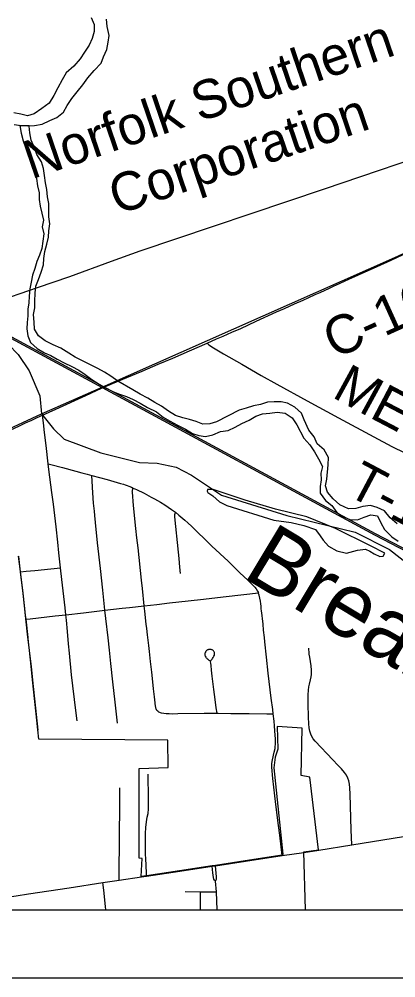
# Model space of a CAD drawing. Extents: x 0 to 34, y 0 to 22.
# Drawn here: x 3.054 to 3.607, y 13.717 to 15.128 of the extents above; entities that cross this region are included whole.
import ezdxf

# ---------------------------------------------------------------- set-up
doc = ezdxf.new("R2010")
doc.units = 0
for name, color, linetype in [('GM_X_City_Street', 7, 'Continuous'), ('GM_X_Corporation', 7, 'Continuous'), ('GM_X_County_Road', 7, 'Continuous'), ('GM_X_County_Road_Text', 7, 'Continuous'), ('GM_X_Major_River', 7, 'Continuous'), ('GM_X_Minor_Lake', 7, 'Continuous'), ('GM_X_Minor_River', 7, 'Continuous'), ('GM_X_Minor_River_Text', 7, 'Continuous'), ('GM_X_Rail_Line', 7, 'Continuous'), ('GM_X_Rail_Line_Text', 7, 'Continuous'), ('GM_X_State_Route', 7, 'Continuous'), ('GM_X_Township_Road', 7, 'Continuous'), ('GM_X_Township_Road_Text', 7, 'Continuous'), ('SH_Data', 7, 'Continuous')]:
    doc.layers.add(name, color=color, linetype=linetype)

msp = doc.modelspace()

# ---------------------------------------------------------------- linework, layer by layer
at = {"layer": 'GM_X_City_Street'}
for points in [[(3.2006, 13.8608), (3.2006, 13.8697), (3.2016, 13.974), (3.2016, 13.997)], [(3.3424, 13.8596), (3.3409, 13.8607), (3.3398, 13.8624), (3.3394, 13.8647), (3.3385, 13.8715), (3.3374, 13.8814)], [(3.3424, 13.8596), (3.3435, 13.8622), (3.3436, 13.8657), (3.3422, 13.8821)], [(3.1808, 13.8173), (3.1805, 13.8222), (3.178, 13.8462), (3.1768, 13.8574)], [(3.3448, 13.8173), (3.3438, 13.8438), (3.3424, 13.8596)], [(3.2976, 13.8441), (3.3201, 13.844), (3.3438, 13.8438)], [(3.3203, 13.8173), (3.3201, 13.8368), (3.3201, 13.844)]]:
    msp.add_lwpolyline(points, dxfattribs=at)
at = {"layer": 'GM_X_Corporation'}
for points in [[(4.732, 17.2135), (3.7259, 17.2107), (3.5941, 17.2097), (3.4848, 17.2088), (3.0597, 17.2067), (2.6493, 17.2102), (2.5952, 17.2097), (2.159, 17.2055), (2.114, 17.2048), (2.114, 13.8173), (5.0539, 13.8173)], [(2.114, 13.8173), (3.4743, 13.8173), (3.472, 13.9024), (3.4938, 13.9058), (3.4807, 14.0124), (3.4679, 14.015), (3.4696, 14.0846), (3.4327, 14.0869), (3.4339, 14.0539), (3.43, 14.0419), (3.4281, 14.0264), (3.4388, 13.9229), (3.4413, 13.8991), (3.4401, 13.8975), (3.386, 13.8896), (3.342, 13.8827), (3.3372, 13.8819), (3.2894, 13.8748), (3.2406, 13.8674), (3.2331, 13.8663), (3.2346, 13.8929), (3.2301, 13.8935), (3.2299, 14.025), (3.2724, 14.0267), (3.2721, 14.0668), (3.0825, 14.0685), (3.0812, 14.0822), (3.0786, 14.1054), (3.0748, 14.1418), (3.0734, 14.1556), (3.0713, 14.1759), (3.0681, 14.2033), (3.0665, 14.2182), (3.0635, 14.2453), (3.0628, 14.2509), (3.0613, 14.2652), (3.0594, 14.2832), (3.0555, 14.3152), (3.0527, 14.3374)]]:
    msp.add_lwpolyline(points, dxfattribs=at)
at = {"layer": 'GM_X_County_Road'}
for points in [[(3.3301, 14.6508), (3.3437, 14.6571), (3.3533, 14.6613), (3.3664, 14.667), (3.3795, 14.6727), (3.402, 14.6832), (3.4318, 14.6969), (3.4437, 14.7021), (3.4584, 14.7087), (3.4709, 14.7144), (3.4796, 14.7183), (3.4886, 14.7224), (3.4961, 14.7256), (3.5099, 14.732), (3.5158, 14.7347), (3.5255, 14.7392), (3.5381, 14.7449), (3.5525, 14.7514), (3.5744, 14.7611), (3.6003, 14.7732), (3.6263, 14.7851)], [(3.0879, 14.545), (3.1073, 14.5538), (3.1516, 14.5741), (3.1747, 14.5845), (3.1907, 14.5915), (3.2119, 14.6002), (3.2344, 14.6097), (3.2581, 14.62), (3.2793, 14.629), (3.304, 14.6396), (3.3301, 14.6508)], [(3.0404, 14.5231), (3.0529, 14.5289), (3.0628, 14.5335), (3.0723, 14.5378), (3.0802, 14.5414), (3.0879, 14.545)]]:
    msp.add_lwpolyline(points, dxfattribs=at)
at = {"layer": 'GM_X_Major_River'}
for points in [[(3.046, 14.9726), (3.0558, 14.9711), (3.066, 14.9708), (3.0763, 14.9713), (3.0876, 14.9733), (3.0985, 14.9783), (3.1087, 14.9829), (3.1189, 14.9909), (3.1241, 15.0008), (3.1308, 15.0111), (3.1387, 15.0207), (3.147, 15.031), (3.1544, 15.0413), (3.1638, 15.0523), (3.174, 15.0627), (3.1777, 15.0722), (3.1825, 15.0832), (3.1843, 15.0938), (3.1861, 15.1037), (3.183, 15.1166), (3.1818, 15.1276)], [(3.1594, 15.1301), (3.1637, 15.1195), (3.1637, 15.1096), (3.1608, 15.099), (3.1563, 15.0891), (3.1496, 15.0788), (3.1432, 15.0693), (3.1339, 15.0582), (3.1226, 15.0486), (3.1166, 15.0383), (3.1103, 15.0265), (3.1047, 15.0151), (3.0976, 15.004), (3.0867, 14.9964), (3.0757, 14.9883), (3.0656, 14.9852)], [(3.0656, 14.9852), (3.0561, 14.9878), (3.0455, 14.99)]]:
    msp.add_lwpolyline(points, dxfattribs=at)
at = {"layer": 'GM_X_Minor_Lake'}
msp.add_line((3.4766, 14.3956), (3.4303, 14.4066), dxfattribs=at)
msp.add_lwpolyline([(3.4303, 14.4066), (3.386, 14.4199), (3.3389, 14.4355), (3.3302, 14.4358), (3.3298, 14.4331), (3.331, 14.4313), (3.3382, 14.4264), (3.3481, 14.4174), (3.3588, 14.4121), (3.4278, 14.3907), (3.4532, 14.3871), (3.4722, 14.3827), (3.4892, 14.3767), (3.4961, 14.3677), (3.5003, 14.3609), (3.5084, 14.3522), (3.5205, 14.3455), (3.5346, 14.3422), (3.5508, 14.3465), (3.5625, 14.3477), (3.5693, 14.3451), (3.5754, 14.341), (3.5838, 14.3369), (3.5887, 14.3377), (3.5909, 14.3422), (3.57, 14.3527), (3.5184, 14.3785), (3.4766, 14.3956)], dxfattribs=at)
at = {"layer": 'GM_X_Minor_River'}
msp.add_line((3.0683, 14.9709), (3.0544, 14.9713), dxfattribs=at)
for points in [[(3.0544, 14.9713), (3.0567, 14.9597), (3.0594, 14.9484), (3.064, 14.9374), (3.0694, 14.9272), (3.0718, 14.9159), (3.0756, 14.9045), (3.0791, 14.8932), (3.0804, 14.8826), (3.0831, 14.8723), (3.0832, 14.8625), (3.0844, 14.8526), (3.0871, 14.842), (3.0891, 14.8318), (3.0873, 14.8219), (3.09, 14.8117), (3.0882, 14.8011), (3.0871, 14.7904), (3.0834, 14.7806), (3.0793, 14.771), (3.0768, 14.7608), (3.0734, 14.7509), (3.0712, 14.7406), (3.0694, 14.7308), (3.0684, 14.7201), (3.0677, 14.7103), (3.0662, 14.7008), (3.0663, 14.6913), (3.0653, 14.6814), (3.0646, 14.6719), (3.0662, 14.6617), (3.0704, 14.6519), (3.0799, 14.6432), (3.0906, 14.6369), (3.1001, 14.6328), (3.1096, 14.6272), (3.1198, 14.6219), (3.1309, 14.6167), (3.1411, 14.6111), (3.1506, 14.6047), (3.1605, 14.5976), (3.1712, 14.5908), (3.1807, 14.5852), (3.1913, 14.5796), (3.2012, 14.5759), (3.2114, 14.5726), (3.2213, 14.5681), (3.2312, 14.5629), (3.2422, 14.5561), (3.2555, 14.5498), (3.2654, 14.5423), (3.2757, 14.5363), (3.2863, 14.5303), (3.2981, 14.5243), (3.3084, 14.5179), (3.3179, 14.515), (3.3277, 14.5135), (3.3383, 14.5163), (3.3496, 14.5209), (3.3606, 14.5225), (3.3711, 14.5275), (3.3809, 14.5329), (3.3915, 14.5379), (3.4013, 14.5433), (3.4111, 14.5472), (3.4221, 14.548), (3.433, 14.5492), (3.4444, 14.5478), (3.455, 14.5411), (3.4616, 14.5309), (3.4723, 14.5112), (3.4807, 14.5014), (3.4876, 14.4913), (3.4937, 14.4807), (3.4995, 14.4697), (3.4969, 14.4595), (3.4974, 14.45), (3.4959, 14.4401), (3.496, 14.4303), (3.5037, 14.4197), (3.5132, 14.4122), (3.5208, 14.402), (3.5304, 14.3953), (3.5398, 14.3915), (3.5508, 14.3912), (3.5606, 14.3951), (3.5705, 14.3982), (3.5803, 14.3968), (3.5853, 14.3866), (3.5907, 14.3768), (3.6014, 14.3662), (3.6109, 14.3595)], [(3.4481, 14.5626), (3.4386, 14.5645), (3.4284, 14.5648), (3.4185, 14.5639), (3.4083, 14.5608), (3.3981, 14.5585), (3.3872, 14.5553), (3.377, 14.5522), (3.3438, 14.5353), (3.334, 14.5322), (3.3238, 14.5317), (3.3139, 14.5358), (3.3041, 14.5384), (3.2942, 14.541), (3.2836, 14.5443), (3.2729, 14.5507), (3.263, 14.5582), (3.2531, 14.5638), (3.2425, 14.5698), (3.2315, 14.5761), (3.2208, 14.5821), (3.1988, 14.5948), (3.1885, 14.6023), (3.179, 14.6083), (3.1691, 14.6136), (3.1573, 14.6196), (3.1478, 14.6244), (3.1361, 14.6304), (3.1265, 14.636), (3.1148, 14.6435), (3.1034, 14.6487), (3.092, 14.6543), (3.0821, 14.6615), (3.0759, 14.6716), (3.0755, 14.6819), (3.0746, 14.6933), (3.0764, 14.7031), (3.0764, 14.7126), (3.077, 14.7244), (3.0781, 14.735), (3.0822, 14.7445), (3.0859, 14.7555), (3.0892, 14.7662), (3.0899, 14.7757), (3.0913, 14.7859), (3.0943, 14.7966), (3.0968, 14.8068), (3.0971, 14.8163), (3.0986, 14.8266), (3.097, 14.8368), (3.0973, 14.8467), (3.0972, 14.8565), (3.0952, 14.8664), (3.0944, 14.877), (3.0924, 14.8868), (3.0908, 14.8978), (3.0892, 14.9077), (3.0865, 14.9179), (3.0796, 14.9284), (3.0761, 14.9383), (3.0711, 14.9496), (3.0692, 14.9602), (3.0683, 14.9704), (3.0683, 14.9709)], [(3.6092, 14.3852), (3.5992, 14.3939), (3.5905, 14.4041), (3.5798, 14.4093), (3.57, 14.4119), (3.5586, 14.4106), (3.5484, 14.4075), (3.5378, 14.4071), (3.5249, 14.413), (3.5154, 14.4217), (3.507, 14.4315), (3.5039, 14.4413), (3.5057, 14.4508), (3.5078, 14.4721), (3.5081, 14.4827), (3.502, 14.494), (3.4917, 14.503), (3.4874, 14.5133), (3.4794, 14.5231), (3.4725, 14.5382), (3.4686, 14.548), (3.4587, 14.557), (3.4481, 14.5626)]]:
    msp.add_lwpolyline(points, dxfattribs=at)
at = {"layer": 'GM_X_Rail_Line'}
msp.add_line((3.0863, 14.5472), (3.1757, 14.5864), dxfattribs=at)
for points in [[(3.0149, 14.7105), (3.0803, 14.7326), (3.128, 14.7488), (3.1891, 14.7717), (3.2313, 14.7866), (3.5025, 14.8781), (3.6902, 14.9419)], [(3.1757, 14.5864), (3.6056, 14.777), (3.709, 14.8243), (3.8008, 14.858), (3.9746, 14.9077), (4.0254, 14.9101), (4.301, 14.9178), (4.3473, 14.9048), (4.5823, 14.8024), (4.7517, 14.7573), (4.9245, 14.7137), (5.0662, 14.6846), (5.2252, 14.6792), (5.2963, 14.6779)], [(2.9747, 14.6894), (3.0232, 14.6639), (3.0523, 14.6345), (3.0682, 14.6103), (3.0838, 14.5735), (3.0863, 14.5472)], [(4.608, 13.8331), (4.5607, 13.8486), (4.517, 13.8684), (4.4694, 13.8906), (4.4269, 13.9136), (4.0464, 14.124), (3.5762, 14.3684), (3.1759, 14.5851), (3.0416, 14.6578)], [(4.6088, 13.8353), (4.5616, 13.8508), (4.5179, 13.8705), (4.4705, 13.8927), (4.4281, 13.9157), (4.0475, 14.126), (3.5773, 14.3705), (3.177, 14.5871), (3.0427, 14.6599)], [(2.114, 14.2044), (2.3759, 14.309), (2.8221, 14.4454), (3.0247, 14.5187), (3.0863, 14.5472)], [(3.0863, 14.5472), (3.1041, 14.5249), (3.1199, 14.5095), (3.1737, 14.4896), (3.2303, 14.4753), (3.2566, 14.4744), (3.2842, 14.4686), (3.3069, 14.4566), (3.351, 14.4272), (3.4469, 14.3972), (3.5477, 14.3728), (3.598, 14.3474), (3.6632, 14.2963), (3.7477, 14.2257), (3.826, 14.1572), (3.8816, 14.1151), (4.0933, 13.9137), (4.1465, 13.842), (4.1621, 13.8173)]]:
    msp.add_lwpolyline(points, dxfattribs=at)
at = {"layer": 'GM_X_State_Route'}
for p, q in [((3.4404, 13.897), (3.4722, 13.9018)), ((3.4722, 13.9018), (3.494, 13.9052))]:
    msp.add_line(p, q, dxfattribs=at)
for points in [[(3.494, 13.9052), (3.5427, 13.9129), (3.6188, 13.925), (3.6622, 13.932), (3.7942, 13.952), (3.9385, 13.974)], [(3.2333, 13.8657), (3.2408, 13.8669), (3.2896, 13.8742), (3.3374, 13.8814), (3.3422, 13.8821), (3.3862, 13.889), (3.4404, 13.897)], [(3.0224, 13.834), (3.0332, 13.8354), (3.0493, 13.8379), (3.0675, 13.8408), (3.1269, 13.8499), (3.1768, 13.8574), (3.2006, 13.8608), (3.2333, 13.8657)]]:
    msp.add_lwpolyline(points, dxfattribs=at)
at = {"layer": 'GM_X_Township_Road'}
for points in [[(3.3301, 14.6508), (3.3317, 14.6492), (3.3334, 14.6478), (3.3369, 14.6455), (3.3538, 14.6354), (3.3807, 14.6202), (3.4091, 14.6036), (3.4324, 14.5906), (3.4771, 14.5662), (3.5228, 14.5412), (3.5751, 14.513), (3.6015, 14.4991), (3.6203, 14.4895)], [(3.0963, 14.4736), (3.0932, 14.5002), (3.0909, 14.5193), (3.0893, 14.5335), (3.0879, 14.545)], [(3.0963, 14.4736), (3.1, 14.4726), (3.1171, 14.468), (3.137, 14.4626), (3.1456, 14.4602), (3.1535, 14.458), (3.1606, 14.4561)], [(3.1141, 14.3203), (3.1119, 14.3424), (3.1104, 14.3583), (3.108, 14.3806), (3.1042, 14.414), (3.1018, 14.4312), (3.0973, 14.465), (3.0963, 14.4736)], [(3.1606, 14.4561), (3.183, 14.4502), (3.2027, 14.4447), (3.2071, 14.4433), (3.2093, 14.4426), (3.2124, 14.4415), (3.2148, 14.4405), (3.2185, 14.439), (3.2212, 14.4378)], [(3.1795, 14.2583), (3.1765, 14.2877), (3.1732, 14.3192), (3.1689, 14.3574), (3.1658, 14.3871), (3.1648, 14.3972), (3.1641, 14.4038), (3.163, 14.4155), (3.162, 14.431), (3.1609, 14.4478), (3.1606, 14.4561)], [(3.2375, 14.2646), (3.2347, 14.2899), (3.2332, 14.3022), (3.2285, 14.3498), (3.2267, 14.3645), (3.2253, 14.3782), (3.2218, 14.4123), (3.22, 14.4315), (3.2199, 14.4327), (3.22, 14.4337), (3.2202, 14.4347), (3.2212, 14.4378)], [(3.2212, 14.4378), (3.2262, 14.4356), (3.2371, 14.4302), (3.2476, 14.4246), (3.2525, 14.422), (3.2614, 14.4169), (3.2679, 14.4129), (3.2727, 14.4098), (3.2775, 14.4064), (3.2832, 14.4021)], [(3.2907, 14.312), (3.2899, 14.3214), (3.2887, 14.3342), (3.2879, 14.3433), (3.2826, 14.3956), (3.2826, 14.3987), (3.2827, 14.4003), (3.2832, 14.4021)], [(3.2832, 14.4021), (3.2883, 14.398), (3.2969, 14.3907), (3.3013, 14.3868), (3.3075, 14.381), (3.3119, 14.3769), (3.3304, 14.3587)], [(3.3304, 14.3587), (3.3368, 14.3524), (3.3608, 14.33), (3.3781, 14.3129), (3.3896, 14.3024), (3.3926, 14.2995), (3.3963, 14.2958), (3.3982, 14.2938), (3.3999, 14.2918), (3.4019, 14.2893), (3.4038, 14.2863), (3.4053, 14.2836)], [(3.0557, 14.3146), (3.0529, 14.3369), (3.0528, 14.3378)], [(3.0557, 14.3146), (3.0637, 14.3154), (3.0766, 14.3166), (3.1003, 14.3189), (3.1141, 14.3203)], [(3.0637, 14.2448), (3.063, 14.2504), (3.0615, 14.2646), (3.0596, 14.2827), (3.0557, 14.3146)], [(3.1222, 14.2514), (3.121, 14.2616), (3.119, 14.2784), (3.1161, 14.3031), (3.1141, 14.3203)], [(3.2375, 14.2646), (3.2558, 14.2666), (3.2745, 14.2689), (3.2884, 14.2704), (3.32, 14.2737), (3.358, 14.2781), (3.4053, 14.2836)], [(3.4174, 14.1891), (3.4149, 14.2118), (3.4142, 14.2178), (3.413, 14.2289), (3.4121, 14.2376), (3.4112, 14.2459), (3.4107, 14.2498), (3.4103, 14.2543), (3.41, 14.2568), (3.4095, 14.2608), (3.4091, 14.264), (3.4087, 14.2673), (3.4082, 14.2714), (3.4074, 14.276), (3.4064, 14.2802), (3.4059, 14.2819), (3.4053, 14.2836)], [(3.0637, 14.2448), (3.0698, 14.2455), (3.1065, 14.2497), (3.1222, 14.2514), (3.1483, 14.2544), (3.1795, 14.2583)], [(3.1795, 14.2583), (3.2048, 14.261), (3.2159, 14.2622), (3.2375, 14.2646)], [(3.198, 14.0918), (3.1946, 14.1226), (3.1912, 14.1528), (3.1883, 14.1796), (3.1862, 14.1992), (3.1842, 14.2174), (3.1809, 14.2457), (3.1795, 14.2583)], [(3.2584, 14.1087), (3.2572, 14.1094), (3.2561, 14.1104), (3.2554, 14.1116), (3.2549, 14.1128), (3.2546, 14.114), (3.2545, 14.1153), (3.2542, 14.1165), (3.2535, 14.122), (3.2525, 14.1306), (3.2511, 14.1423), (3.25, 14.1528), (3.2485, 14.1671), (3.2468, 14.1825), (3.2451, 14.1973), (3.2442, 14.206), (3.2423, 14.222), (3.2412, 14.2312), (3.2405, 14.2374), (3.2384, 14.2565), (3.2375, 14.2646)], [(3.0668, 14.2167), (3.0667, 14.2177), (3.0637, 14.2448)], [(3.139, 14.0953), (3.1371, 14.1107), (3.1307, 14.1631), (3.1274, 14.1951), (3.1263, 14.2087), (3.1247, 14.2266), (3.123, 14.2433), (3.1222, 14.2514)], [(3.0814, 14.0817), (3.0788, 14.1048), (3.075, 14.1413), (3.0736, 14.155), (3.0715, 14.1753), (3.0683, 14.2027), (3.0668, 14.2167)], [(3.5427, 13.9129), (3.5415, 13.9352), (3.5403, 13.9874), (3.5398, 13.9966), (3.5392, 14.0021), (3.5382, 14.0069), (3.5368, 14.0109), (3.5346, 14.0152), (3.5319, 14.0192), (3.5273, 14.0249), (3.5222, 14.0303), (3.5147, 14.0378), (3.4886, 14.0654), (3.4859, 14.0689), (3.4838, 14.0722), (3.4822, 14.0756), (3.4808, 14.0799), (3.4799, 14.0849), (3.4792, 14.0911), (3.4787, 14.1005), (3.4784, 14.1204), (3.4784, 14.1335), (3.4788, 14.1404), (3.4795, 14.1454), (3.4802, 14.1491), (3.482, 14.1557), (3.4828, 14.1601), (3.4832, 14.1635), (3.4833, 14.1699), (3.483, 14.1763), (3.4809, 14.1891), (3.4801, 14.1934), (3.4797, 14.1967), (3.4796, 14.1999), (3.4796, 14.2023)], [(3.3444, 14.1065), (3.3433, 14.1146), (3.3418, 14.1265), (3.3398, 14.1415), (3.3373, 14.161), (3.3363, 14.17), (3.3356, 14.1765), (3.3351, 14.1804), (3.335, 14.1821), (3.335, 14.1831), (3.3352, 14.1838), (3.3357, 14.1845), (3.3363, 14.1851), (3.3372, 14.1859), (3.338, 14.1868), (3.3389, 14.1883), (3.3399, 14.1904), (3.3405, 14.1921), (3.3408, 14.1933), (3.3408, 14.194), (3.3408, 14.1946), (3.3407, 14.1954), (3.3405, 14.1961), (3.3402, 14.1968), (3.3398, 14.1974), (3.3393, 14.1981), (3.3387, 14.1987), (3.3381, 14.1991), (3.3375, 14.1996), (3.3367, 14.1999), (3.336, 14.2002), (3.3352, 14.2004), (3.3344, 14.2005), (3.3336, 14.2005), (3.3328, 14.2004), (3.332, 14.2002), (3.3313, 14.2), (3.3305, 14.1996), (3.3298, 14.1991), (3.3292, 14.1987), (3.3286, 14.1982), (3.3278, 14.1973), (3.3271, 14.196), (3.3269, 14.1953), (3.3267, 14.1945), (3.3266, 14.1936), (3.3265, 14.1928), (3.3266, 14.1921), (3.3268, 14.1912), (3.327, 14.1906), (3.3278, 14.1892), (3.3285, 14.1882), (3.3293, 14.1873), (3.3299, 14.1867), (3.3307, 14.1861), (3.3319, 14.1851), (3.3324, 14.1848), (3.3341, 14.184)], [(3.4271, 14.1058), (3.4264, 14.112), (3.4242, 14.1286), (3.4198, 14.1656), (3.4174, 14.1891)], [(3.2584, 14.1087), (3.2623, 14.1073), (3.266, 14.1066), (3.2697, 14.1062), (3.274, 14.1059), (3.2784, 14.1058), (3.2868, 14.106), (3.3257, 14.1066), (3.3444, 14.1065)], [(3.3444, 14.1065), (3.3462, 14.1065), (3.3649, 14.1061), (3.3916, 14.106), (3.4177, 14.1058), (3.4271, 14.1058)], [(3.4404, 13.897), (3.4367, 13.9272), (3.435, 13.9413), (3.431, 13.9721), (3.4265, 14.0104), (3.4251, 14.0271), (3.4252, 14.0325), (3.4259, 14.0379), (3.4286, 14.0492), (3.4297, 14.0545), (3.4301, 14.0575), (3.4304, 14.0603), (3.4305, 14.063), (3.4304, 14.0657), (3.4303, 14.0688), (3.43, 14.0743), (3.4296, 14.0807), (3.4291, 14.0879), (3.4283, 14.0948), (3.4271, 14.1058)], [(3.2408, 13.8669), (3.2406, 13.8701), (3.2401, 13.8837), (3.2396, 13.8917), (3.2394, 13.8998), (3.2393, 13.9297), (3.2398, 13.9382), (3.2407, 13.9469), (3.2419, 13.9536), (3.243, 13.9591), (3.2435, 13.966), (3.2437, 13.9721), (3.2437, 13.9808), (3.2432, 14.0168)]]:
    msp.add_lwpolyline(points, dxfattribs=at)
at = {"layer": 'SH_Data'}
for p, q in [((2.114, 13.8173), (8.914, 13.8173)), ((2.014, 13.7173), (9.014, 13.7173))]:
    msp.add_line(p, q, dxfattribs=at)

# ---------------------------------------------------------------- texts
at = {"layer": 'GM_X_County_Road_Text'}
msp.add_text('C-162', height=0.05682, rotation=24.353, dxfattribs=at).set_placement((3.5172, 14.6271))
at = {"layer": 'GM_X_Minor_River_Text'}
msp.add_text('Breakneck', height=0.09474, rotation=328.9739, dxfattribs=at).set_placement((3.3796, 14.3079))
at = {"layer": 'GM_X_Rail_Line_Text'}
for s, rotation, p in [('Norfolk Southern', 18.8751, (3.0715, 14.8916)), ('Corporation', 18.8064, (3.1976, 14.8393))]:
    msp.add_text(s, height=0.056629, rotation=rotation, dxfattribs=at).set_placement(p)
at = {"layer": 'GM_X_Township_Road_Text'}
for s, height, rotation, p in [('M', 0.0568, 331.4228, (3.5119, 14.5723)), ('E', 0.0568, 332.31, (3.5669, 14.5424)), ('T-152', 0.05682, 332.0261, (3.5324, 14.4293))]:
    msp.add_text(s, height=height, rotation=rotation, dxfattribs=at).set_placement(p)

doc.saveas('drawing.dxf')
